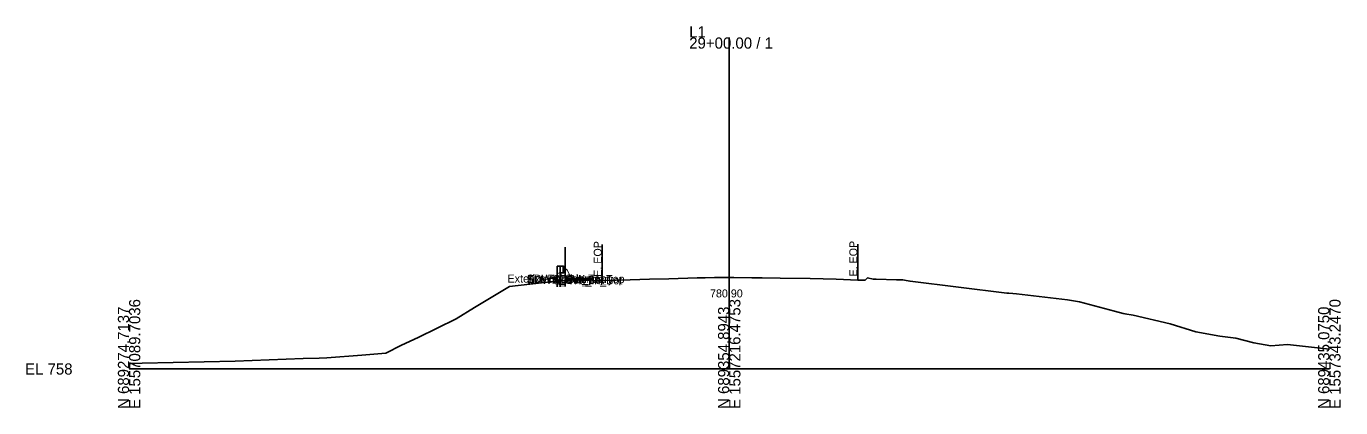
# Model space of a CAD drawing. Extents: x -26 to 2603, y -3010 to 9589.
# Drawn here: x 974.3 to 1302.8, y 2490.3 to 2585.7 of the extents above; entities that cross this region are included whole.
import ezdxf

# ---------------------------------------------------------------- set-up
doc = ezdxf.new("R2010")
doc.units = 0
for name, color, linetype in [('Default', 7, 'Continuous'), ('Exist Cross Section Cell', 7, 'Continuous'), ('Exist XS Center Line Elevation Label', 7, 'Continuous'), ('Exist XS Ground Line', 7, 'Continuous'), ('Prop CMT Conc Surface', 7, 'Continuous'), ('Prop CMT Concrete Structures', 7, 'Continuous'), ('Prop CMT Slope Grass', 7, 'Continuous'), ('Prop XS Earthwork Shape', 7, 'Continuous'), ('Prop XS Label Text', 7, 'Continuous'), ('Prop XS Side Slope Text', 7, 'Continuous'), ('Scratch_Level_1', 7, 'Continuous'), ('Typical Guardrail CELL', 7, 'Continuous')]:
    doc.layers.add(name, color=color, linetype=linetype)

msp = doc.modelspace()

# ---------------------------------------------------------------- linework, layer by layer
at = {"layer": 'Exist Cross Section Cell'}
for p, q in [((1150, 2500), (1150, 2582.92)), ((1000, 2500), (1150, 2500)), ((1150, 2500), (1300, 2500))]:
    msp.add_line(p, q, dxfattribs=at)
at = {"layer": 'Exist XS Ground Line'}
msp.add_lwpolyline([(1000, 2501.37), (1000.46, 2501.38), (1001.4, 2501.4), (1003.31, 2501.42), (1026.55, 2501.94), (1043.5, 2502.6), (1047.52, 2502.72), (1049.44, 2502.76), (1058.17, 2503.43), (1064.15, 2503.92), (1068.06, 2505.99), (1072.27, 2507.84), (1081.75, 2512.53), (1086.33, 2515.36), (1095.1, 2520.6), (1105.97, 2521.85), (1106.74, 2521.94), (1107.11, 2521.99), (1112.88, 2522.36), (1113.72, 2522.34), (1115.45, 2522.51), (1116.07, 2522.05), (1117.03, 2522.11), (1118.24, 2522.14), (1125.22, 2522.26), (1130.08, 2522.45), (1134.89, 2522.55), (1142.02, 2522.78), (1143.97, 2522.82), (1146.35, 2522.87), (1148.47, 2522.88), (1150, 2522.9), (1151.13, 2522.91), (1155.69, 2522.83), (1158.2, 2522.81), (1162.7, 2522.73), (1170.2, 2522.59), (1176.69, 2522.47), (1182.13, 2522.21), (1183.95, 2522.19), (1184.6, 2522.76), (1186.02, 2522.48), (1186.71, 2522.46), (1191.8, 2522.31), (1193.39, 2522.28), (1194.21, 2522.15), (1195.22, 2521.95), (1219.41, 2518.98), (1219.9, 2518.93), (1220.91, 2518.85), (1221.81, 2518.81), (1234.58, 2517.28), (1237.59, 2516.81), (1246.34, 2514.45), (1248.45, 2513.89), (1248.91, 2513.82), (1250.95, 2513.44), (1260.24, 2511.3), (1266.59, 2509.26), (1272.66, 2508.2), (1276.6, 2507.68), (1281.14, 2506.52), (1285.4, 2505.78), (1289.5, 2506.11), (1300, 2504.97)], dxfattribs=at)
at = {"layer": 'Prop CMT Conc Surface'}
msp.add_lwpolyline([(1115.46, 2522.51), (1110.46, 2522.61)], dxfattribs=at)
at = {"layer": 'Prop CMT Concrete Structures'}
for points in [[(1110.46, 2522.27), (1110.46, 2522.61)], [(1110.46, 2522.61), (1115.46, 2522.51)], [(1115.46, 2522.17), (1110.46, 2522.27)], [(1115.46, 2522.51), (1115.46, 2522.17)]]:
    msp.add_lwpolyline(points, dxfattribs=at)
at = {"layer": 'Prop CMT Slope Grass'}
for p, q in [((1109.96, 2522.62), (1108.94, 2522.11)), ((1110.46, 2522.61), (1109.96, 2522.62))]:
    msp.add_line(p, q, dxfattribs=at)
at = {"layer": 'Prop XS Earthwork Shape'}
for points in [[(1108.94, 2522.11), (1111.29, 2522.26), (1110.46, 2522.27), (1110.46, 2522.61), (1109.96, 2522.62)], [(1115.46, 2522.51), (1115.46, 2522.17), (1111.29, 2522.26), (1112.88, 2522.36), (1113.72, 2522.34)]]:
    msp.add_lwpolyline(points, close=True, dxfattribs=at)
at = {"layer": 'Prop XS Label Text'}
for p, q in [((1118.24, 2531.14), (1118.24, 2522.14)), ((1182.13, 2531.21), (1182.13, 2522.21))]:
    msp.add_line(p, q, dxfattribs=at)
at = {"layer": 'Scratch_Level_1'}
msp.add_line((1109.01, 2520.6), (1109.01, 2530.43), dxfattribs=at)
at = {"layer": 'Typical Guardrail CELL'}
for p, q in [((1107.78, 2525.75), (1107.03, 2525.75)), ((1107.03, 2525.75), (1107.03, 2522.02)), ((1107.78, 2525.75), (1107.78, 2522.02)), ((1107.78, 2525.75), (1108.52, 2525.75)), ((1107.78, 2524.01), (1108.52, 2524.01)), ((1108.52, 2525.75), (1108.52, 2524.01)), ((1108.52, 2525.75), (1108.96, 2525.44)), ((1108.52, 2524.95), (1108.96, 2525.25)), ((1108.52, 2524.88), (1108.52, 2524.95)), ((1108.52, 2524.88), (1108.52, 2524.81)), ((1108.52, 2524.81), (1108.96, 2524.5)), ((1108.52, 2524.01), (1108.96, 2524.31)), ((1107.78, 2522.02), (1107.03, 2522.02)), ((1107.03, 2522.02), (1107.03, 2520.51)), ((1107.78, 2522.02), (1107.78, 2520.51))]:
    msp.add_line(p, q, dxfattribs=at)
for centre, start, end in [((1108.89, 2525.35), 304.9888, 54.997), ((1108.89, 2524.41), 304.9634, 54.9941)]:
    msp.add_arc(centre, 0.116, start, end, dxfattribs=at)

# ---------------------------------------------------------------- texts
at = {"layer": 'Default'}
for s, height, p in [('Exterior Boundary', 2, (1094.6, 2521.61)), ('SDWK_Out_Top', 2, (1099.38, 2521.61)), ('SDWK_Out_Bot', 2, (1099.42, 2521.27)), ('Exterior Boundary', 2, (1099.6, 2521.51)), ('SDWK_In_Top', 2, (1106.01, 2521.51)), ('SDWK_In_Bot', 2, (1106.04, 2521.17)), ('-', 0.0001, (1000, 2500))]:
    msp.add_text(s, height=height, dxfattribs=at).set_placement(p)
at = {"layer": 'Exist Cross Section Cell'}
for s, p in [('L1', (1140, 2582.92)), ('29+00.00 / 1', (1140, 2580.12)), ('EL 758', (974, 2498.6))]:
    msp.add_text(s, height=2.8, dxfattribs=at).set_placement(p)
for s, p in [('E 1557089.7036', (1002.8, 2490)), ('E 1557216.4753', (1152.8, 2490)), ('E 1557343.2470', (1302.8, 2490)), ('N 689274.7137', (1000, 2490)), ('N 689354.8943', (1150, 2490)), ('N 689435.0750', (1300, 2490))]:
    msp.add_text(s, height=2.8, rotation=90, dxfattribs=at).set_placement(p)
at = {"layer": 'Exist XS Center Line Elevation Label'}
msp.add_text('780.90', height=2, dxfattribs=at).set_placement((1145.2, 2517.9))
at = {"layer": 'Prop XS Label Text'}
for p in [(1118.14, 2523.06), (1182.03, 2523.13)]:
    msp.add_text('E. EOP', height=2, rotation=90, dxfattribs=at).set_placement(p)
at = {"layer": 'Prop XS Side Slope Text'}
msp.add_text('2:1', height=2, rotation=26.5651, dxfattribs=at).set_placement((1107.53, 2521.92))

doc.saveas('drawing.dxf')
